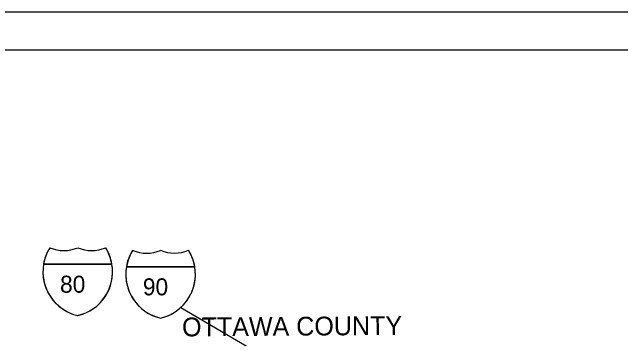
# Model space of a CAD drawing. Extents: x 0 to 798, y 0 to 440.
# Drawn here: x 124.4 to 286.7, y 353 to 440 of the extents above; entities that cross this region are included whole.
import ezdxf

# ---------------------------------------------------------------- set-up
doc = ezdxf.new("R2010")
doc.units = 0
for name, color, linetype in [('GM_X_Adjacent_County_Text', 7, 'Continuous'), ('GM_X_Interstate_Route', 7, 'Continuous'), ('PV_P_Text', 7, 'Continuous'), ('SH_Border', 7, 'Continuous'), ('SH_Cut_Line', 7, 'Continuous')]:
    doc.layers.add(name, color=color, linetype=linetype)

msp = doc.modelspace()

# ---------------------------------------------------------------- linework, layer by layer
at = {"layer": 'GM_X_Interstate_Route'}
msp.add_lwpolyline([(169.37, 361.38), (188.31, 350.22), (191.79, 348.07), (192.46, 347.66), (193.36, 347.1), (194.03, 346.68), (194.19, 346.58), (196.95, 344.88), (203.35, 340.92), (205.03, 339.88), (205.6, 339.54), (206.05, 339.26), (207.28, 338.49), (208.21, 337.92), (210.55, 336.46), (216.7, 332.66), (218.5, 331.55), (220.95, 329.93)], dxfattribs=at)
at = {"layer": 'PV_P_Text'}
for p, q in [((132.73, 372.89), (150.97, 372.89)), ((150.97, 372.89), (132.73, 372.89)), ((150.97, 372.89), (132.73, 372.89)), ((154.82, 372.2), (173.06, 372.2)), ((173.06, 372.2), (154.82, 372.2)), ((173.06, 372.2), (154.82, 372.2))]:
    msp.add_line(p, q, dxfattribs=at)
for centre, radius, start, end in [((144.55, 370.88), 11.99, 147.8216, 256.9941), ((143.8, 371.09), 11.22, 146.654, 170.759), ((138.13, 386.08), 9.57, 247.0848, 292.9105), ((138.13, 386.08), 9.57, 247.0848, 292.9105), ((139.15, 370.88), 11.99, 283.0065, 32.1787), ((145.58, 386.08), 9.57, 247.0916, 292.9084), ((145.58, 386.08), 9.57, 247.0916, 292.9084), ((139.15, 370.88), 11.99, 9.6475, 32.179), ((166.64, 370.19), 11.99, 147.8216, 256.9941), ((165.89, 370.4), 11.22, 146.654, 170.759), ((160.21, 385.38), 9.57, 247.0848, 292.9105), ((160.21, 385.38), 9.57, 247.0848, 292.9105), ((161.24, 370.19), 11.99, 283.0065, 32.1787), ((167.66, 385.39), 9.57, 247.0916, 292.9084), ((167.66, 385.39), 9.57, 247.0916, 292.9084), ((161.24, 370.19), 11.99, 9.6475, 32.179), ((144.55, 370.88), 11.99, 170.3514, 256.9967), ((139.18, 370.88), 11.97, 282.7667, 9.6898), ((166.63, 370.19), 11.99, 170.3514, 256.9967), ((161.26, 370.18), 11.97, 282.7667, 9.6898)]:
    msp.add_arc(centre, radius, start, end, dxfattribs=at)
at = {"layer": 'SH_Border'}
msp.add_lwpolyline([(30, 430), (670, 430), (670, 10), (30, 10)], close=True, dxfattribs=at)
at = {"layer": 'SH_Cut_Line'}
msp.add_lwpolyline([(0, 0), (680, 0), (680, 440), (0, 440)], close=True, dxfattribs=at)

# ---------------------------------------------------------------- texts
at = {"layer": 'GM_X_Adjacent_County_Text'}
msp.add_text('OTTAWA COUNTY', height=5, rotation=0.3988, dxfattribs=at).set_placement((169.68, 353.64))
at = {"layer": 'PV_P_Text'}
for s, p in [('80', (137.13, 365.28)), ('90', (159.22, 364.58))]:
    msp.add_text(s, height=4.528, dxfattribs=at).set_placement(p)

doc.saveas('drawing.dxf')
